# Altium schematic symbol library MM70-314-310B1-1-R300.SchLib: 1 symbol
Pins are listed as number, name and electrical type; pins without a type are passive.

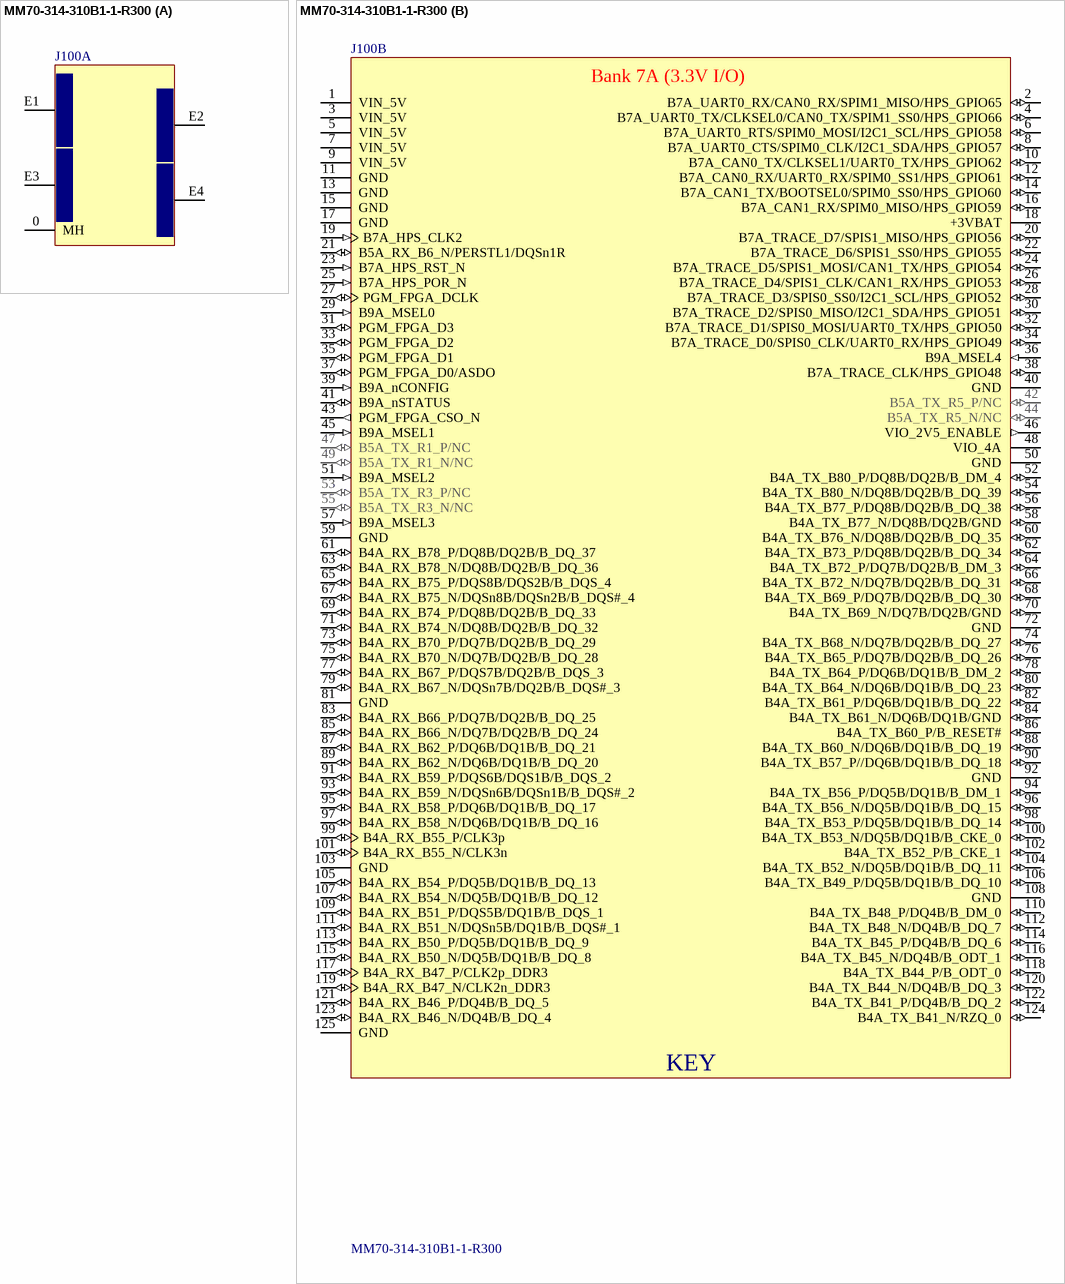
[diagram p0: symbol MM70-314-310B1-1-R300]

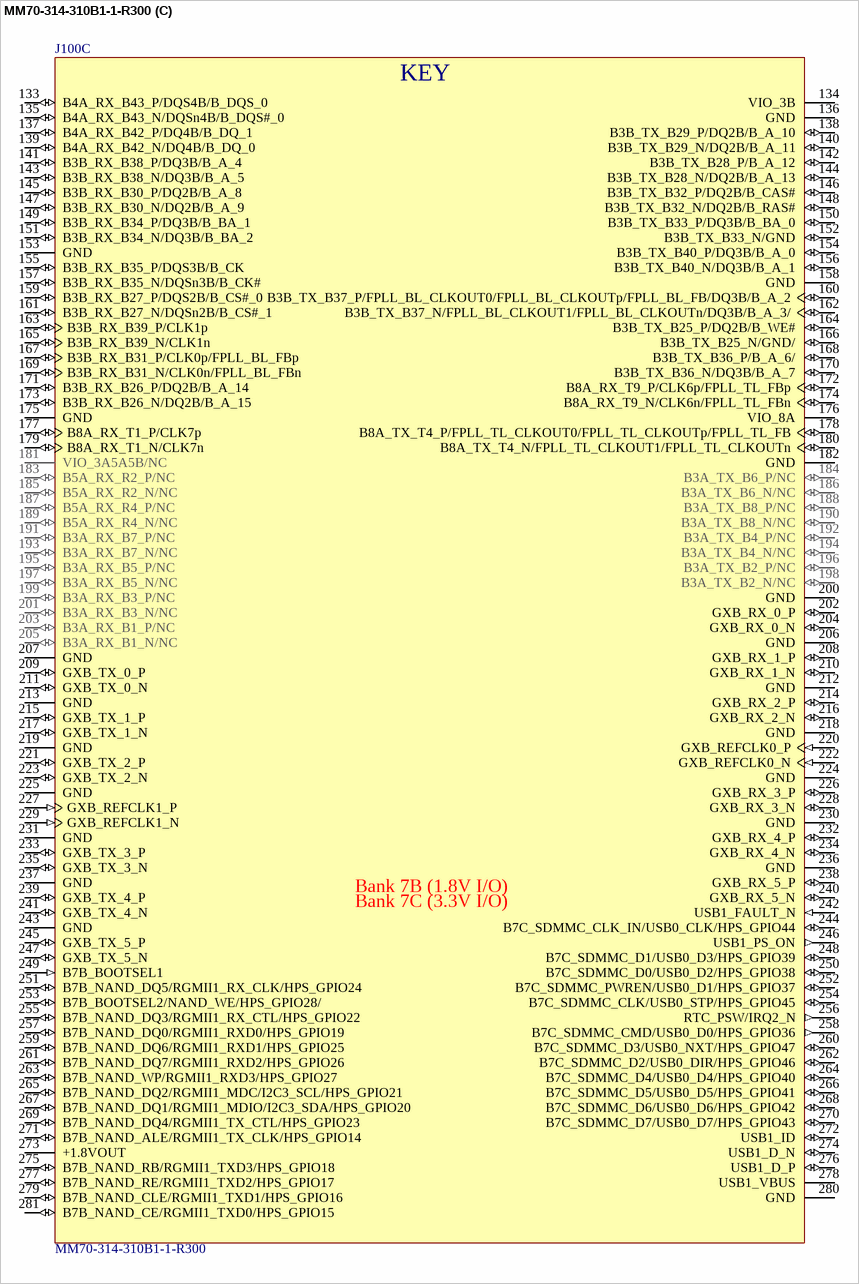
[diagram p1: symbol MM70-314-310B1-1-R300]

## MM70-314-310B1-1-R300
designator J100
MEM SOCKET 314POS RT ANG GOLD; Mfg: JAE Electronics; Dist1_PN: 670-2431-1-ND; Dist1: Digi-Key; User: Huy; $/10: 9.320000; $/100: 6.096200; Mfg_PID: 9534; PbFree_Status: Lead free; QtyAvail: 784; ID: 7823
footprint MM70-314-310B1
part A pins: 0 MH (power), E1 (power), E2 (power), E3 (power), E4 (power)
part B pins: 1 VIN_5V (power), 2 B7A_UART0_RX/CAN0_RX/SPIM1_MISO/HPS_GPIO65 (io), 3 VIN_5V (power), 4 B7A_UART0_TX/CLKSEL0/CAN0_TX/SPIM1_SS0/HPS_GPIO66 (io), 5 VIN_5V (power), 6 B7A_UART0_RTS/SPIM0_MOSI/I2C1_SCL/HPS_GPIO58 (io), 7 VIN_5V (power), 8 B7A_UART0_CTS/SPIM0_CLK/I2C1_SDA/HPS_GPIO57 (io), 9 VIN_5V (power), 10 B7A_CAN0_TX/CLKSEL1/UART0_TX/HPS_GPIO62 (io), 11 GND (power), 12 B7A_CAN0_RX/UART0_RX/SPIM0_SS1/HPS_GPIO61 (io), 13 GND (power), 14 B7A_CAN1_TX/BOOTSEL0/SPIM0_SS0/HPS_GPIO60 (io), 15 GND (power), 16 B7A_CAN1_RX/SPIM0_MISO/HPS_GPIO59 (io), 17 GND (power), 18 +3VBAT (power), 19 B7A_HPS_CLK2 (in), 20 B7A_TRACE_D7/SPIS1_MISO/HPS_GPIO56 (io), 21 B5A_RX_B6_N/PERSTL1/DQSn1R (io), 22 B7A_TRACE_D6/SPIS1_SS0/HPS_GPIO55 (io), 23 B7A_HPS_RST_N (in), 24 B7A_TRACE_D5/SPIS1_MOSI/CAN1_TX/HPS_GPIO54 (io), 25 B7A_HPS_POR_N (in), 26 B7A_TRACE_D4/SPIS1_CLK/CAN1_RX/HPS_GPIO53 (io), 27 PGM_FPGA_DCLK (io), 28 B7A_TRACE_D3/SPIS0_SS0/I2C1_SCL/HPS_GPIO52 (io), 29 B9A_MSEL0 (in), 30 B7A_TRACE_D2/SPIS0_MISO/I2C1_SDA/HPS_GPIO51 (io), 31 PGM_FPGA_D3 (io), 32 B7A_TRACE_D1/SPIS0_MOSI/UART0_TX/HPS_GPIO50 (io), 33 PGM_FPGA_D2 (io), 34 B7A_TRACE_D0/SPIS0_CLK/UART0_RX/HPS_GPIO49 (io), 35 PGM_FPGA_D1 (io), 36 B9A_MSEL4 (in), 37 PGM_FPGA_D0/ASDO (io), 38 B7A_TRACE_CLK/HPS_GPIO48 (io), 39 B9A_nCONFIG (in), 40 GND (power), 41 B9A_nSTATUS (io), 42 B5A_TX_R5_P/NC (io), 43 PGM_FPGA_CSO_N (out), 44 B5A_TX_R5_N/NC (io), 45 B9A_MSEL1 (in), 46 VIO_2V5_ENABLE (out), 47 B5A_TX_R1_P/NC (io), 48 VIO_4A (power), 49 B5A_TX_R1_N/NC (io), 50 GND (power), 51 B9A_MSEL2 (in), 52 B4A_TX_B80_P/DQ8B/DQ2B/B_DM_4 (io), 53 B5A_TX_R3_P/NC (io), 54 B4A_TX_B80_N/DQ8B/DQ2B/B_DQ_39 (io), 55 B5A_TX_R3_N/NC (io), 56 B4A_TX_B77_P/DQ8B/DQ2B/B_DQ_38 (io), 57 B9A_MSEL3 (in), 58 B4A_TX_B77_N/DQ8B/DQ2B/GND (io), 59 GND, 60 B4A_TX_B76_N/DQ8B/DQ2B/B_DQ_35 (io), 61 B4A_RX_B78_P/DQ8B/DQ2B/B_DQ_37 (io), 62 B4A_TX_B73_P/DQ8B/DQ2B/B_DQ_34 (io), 63 B4A_RX_B78_N/DQ8B/DQ2B/B_DQ_36 (io), 64 B4A_TX_B72_P/DQ7B/DQ2B/B_DM_3 (io), 65 B4A_RX_B75_P/DQS8B/DQS2B/B_DQS_4 (io), 66 B4A_TX_B72_N/DQ7B/DQ2B/B_DQ_31 (io), 67 B4A_RX_B75_N/DQSn8B/DQSn2B/B_DQS#_4 (io), 68 B4A_TX_B69_P/DQ7B/DQ2B/B_DQ_30 (io), 69 B4A_RX_B74_P/DQ8B/DQ2B/B_DQ_33 (io), 70 B4A_TX_B69_N/DQ7B/DQ2B/GND (io), 71 B4A_RX_B74_N/DQ8B/DQ2B/B_DQ_32 (io), 72 GND (power), 73 B4A_RX_B70_P/DQ7B/DQ2B/B_DQ_29 (io), 74 B4A_TX_B68_N/DQ7B/DQ2B/B_DQ_27 (io), 75 B4A_RX_B70_N/DQ7B/DQ2B/B_DQ_28 (io), 76 B4A_TX_B65_P/DQ7B/DQ2B/B_DQ_26 (io), 77 B4A_RX_B67_P/DQS7B/DQ2B/B_DQS_3 (io), 78 B4A_TX_B64_P/DQ6B/DQ1B/B_DM_2 (io), 79 B4A_RX_B67_N/DQSn7B/DQ2B/B_DQS#_3 (io), 80 B4A_TX_B64_N/DQ6B/DQ1B/B_DQ_23 (io), 81 GND (power), 82 B4A_TX_B61_P/DQ6B/DQ1B/B_DQ_22 (io), 83 B4A_RX_B66_P/DQ7B/DQ2B/B_DQ_25 (io), 84 B4A_TX_B61_N/DQ6B/DQ1B/GND (io), 85 B4A_RX_B66_N/DQ7B/DQ2B/B_DQ_24 (io), 86 B4A_TX_B60_P/B_RESET# (io), 87 B4A_RX_B62_P/DQ6B/DQ1B/B_DQ_21 (io), 88 B4A_TX_B60_N/DQ6B/DQ1B/B_DQ_19 (io), 89 B4A_RX_B62_N/DQ6B/DQ1B/B_DQ_20 (io), 90 B4A_TX_B57_P//DQ6B/DQ1B/B_DQ_18 (io), 91 B4A_RX_B59_P/DQS6B/DQS1B/B_DQS_2 (io), 92 GND (power), 93 B4A_RX_B59_N/DQSn6B/DQSn1B/B_DQS#_2 (io), 94 B4A_TX_B56_P/DQ5B/DQ1B/B_DM_1 (io), 95 B4A_RX_B58_P/DQ6B/DQ1B/B_DQ_17 (io), 96 B4A_TX_B56_N/DQ5B/DQ1B/B_DQ_15 (io), 97 B4A_RX_B58_N/DQ6B/DQ1B/B_DQ_16 (io), 98 B4A_TX_B53_P/DQ5B/DQ1B/B_DQ_14 (io), 99 B4A_RX_B55_P/CLK3p (io), 100 B4A_TX_B53_N/DQ5B/DQ1B/B_CKE_0 (io), 101 B4A_RX_B55_N/CLK3n (io), 102 B4A_TX_B52_P/B_CKE_1 (io), 103 GND (power), 104 B4A_TX_B52_N/DQ5B/DQ1B/B_DQ_11 (io), 105 B4A_RX_B54_P/DQ5B/DQ1B/B_DQ_13 (io), 106 B4A_TX_B49_P/DQ5B/DQ1B/B_DQ_10 (io), 107 B4A_RX_B54_N/DQ5B/DQ1B/B_DQ_12 (io), 108 GND (power), 109 B4A_RX_B51_P/DQS5B/DQ1B/B_DQS_1 (io), 110 B4A_TX_B48_P/DQ4B/B_DM_0 (io), 111 B4A_RX_B51_N/DQSn5B/DQ1B/B_DQS#_1 (io), 112 B4A_TX_B48_N/DQ4B/B_DQ_7 (io), 113 B4A_RX_B50_P/DQ5B/DQ1B/B_DQ_9 (io), 114 B4A_TX_B45_P/DQ4B/B_DQ_6 (io), 115 B4A_RX_B50_N/DQ5B/DQ1B/B_DQ_8 (io), 116 B4A_TX_B45_N/DQ4B/B_ODT_1 (io), 117 B4A_RX_B47_P/CLK2p_DDR3 (io), 118 B4A_TX_B44_P/B_ODT_0 (io), 119 B4A_RX_B47_N/CLK2n_DDR3 (io), 120 B4A_TX_B44_N/DQ4B/B_DQ_3 (io), 121 B4A_RX_B46_P/DQ4B/B_DQ_5 (io), 122 B4A_TX_B41_P/DQ4B/B_DQ_2 (io), 123 B4A_RX_B46_N/DQ4B/B_DQ_4 (io), 124 B4A_TX_B41_N/RZQ_0 (io), 125 GND (power)
part C pins: 133 B4A_RX_B43_P/DQS4B/B_DQS_0 (io), 134 VIO_3B (power), 135 B4A_RX_B43_N/DQSn4B/B_DQS#_0 (io), 136 GND (power), 137 B4A_RX_B42_P/DQ4B/B_DQ_1 (io), 138 B3B_TX_B29_P/DQ2B/B_A_10 (io), 139 B4A_RX_B42_N/DQ4B/B_DQ_0 (io), 140 B3B_TX_B29_N/DQ2B/B_A_11 (io), 141 B3B_RX_B38_P/DQ3B/B_A_4 (io), 142 B3B_TX_B28_P/B_A_12 (io), 143 B3B_RX_B38_N/DQ3B/B_A_5 (io), 144 B3B_TX_B28_N/DQ2B/B_A_13 (io), 145 B3B_RX_B30_P/DQ2B/B_A_8 (io), 146 B3B_TX_B32_P/DQ2B/B_CAS# (io), 147 B3B_RX_B30_N/DQ2B/B_A_9 (io), 148 B3B_TX_B32_N/DQ2B/B_RAS# (io), 149 B3B_RX_B34_P/DQ3B/B_BA_1 (io), 150 B3B_TX_B33_P/DQ3B/B_BA_0 (io), 151 B3B_RX_B34_N/DQ3B/B_BA_2 (io), 152 B3B_TX_B33_N/GND (io), 153 GND (power), 154 B3B_TX_B40_P/DQ3B/B_A_0 (io), 155 B3B_RX_B35_P/DQS3B/B_CK (io), 156 B3B_TX_B40_N/DQ3B/B_A_1 (io), 157 B3B_RX_B35_N/DQSn3B/B_CK# (io), 158 GND (power), 159 B3B_RX_B27_P/DQS2B/B_CS#_0 (io), 160 B3B_TX_B37_P/FPLL_BL_CLKOUT0/FPLL_BL_CLKOUTp/FPLL_BL_FB/DQ3B/B_A_2 (io), 161 B3B_RX_B27_N/DQSn2B/B_CS#_1 (io), 162 B3B_TX_B37_N/FPLL_BL_CLKOUT1/FPLL_BL_CLKOUTn/DQ3B/B_A_3/ (io), 163 B3B_RX_B39_P/CLK1p (io), 164 B3B_TX_B25_P/DQ2B/B_WE# (io), 165 B3B_RX_B39_N/CLK1n (io), 166 B3B_TX_B25_N/GND/ (io), 167 B3B_RX_B31_P/CLK0p/FPLL_BL_FBp (io), 168 B3B_TX_B36_P/B_A_6/ (io), 169 B3B_RX_B31_N/CLK0n/FPLL_BL_FBn (io), 170 B3B_TX_B36_N/DQ3B/B_A_7 (io), 171 B3B_RX_B26_P/DQ2B/B_A_14 (io), 172 B8A_RX_T9_P/CLK6p/FPLL_TL_FBp (io), 173 B3B_RX_B26_N/DQ2B/B_A_15 (io), 174 B8A_RX_T9_N/CLK6n/FPLL_TL_FBn (io), 175 GND (power), 176 VIO_8A (power), 177 B8A_RX_T1_P/CLK7p (io), 178 B8A_TX_T4_P/FPLL_TL_CLKOUT0/FPLL_TL_CLKOUTp/FPLL_TL_FB (io), 179 B8A_RX_T1_N/CLK7n (io), 180 B8A_TX_T4_N/FPLL_TL_CLKOUT1/FPLL_TL_CLKOUTn (io), 181 VIO_3A5A5B/NC, 182 GND (power), 183 B5A_RX_R2_P/NC (io), 184 B3A_TX_B6_P/NC (io), 185 B5A_RX_R2_N/NC (io), 186 B3A_TX_B6_N/NC (io), 187 B5A_RX_R4_P/NC (io), 188 B3A_TX_B8_P/NC (io), 189 B5A_RX_R4_N/NC (io), 190 B3A_TX_B8_N/NC (io), 191 B3A_RX_B7_P/NC (io), 192 B3A_TX_B4_P/NC (io), 193 B3A_RX_B7_N/NC (io), 194 B3A_TX_B4_N/NC (io), 195 B3A_RX_B5_P/NC (io), 196 B3A_TX_B2_P/NC (io), 197 B3A_RX_B5_N/NC (io), 198 B3A_TX_B2_N/NC (io), 199 B3A_RX_B3_P/NC (io), 200 GND (power), 201 B3A_RX_B3_N/NC (io), 202 GXB_RX_0_P (io), 203 B3A_RX_B1_P/NC (io), 204 GXB_RX_0_N (io), 205 B3A_RX_B1_N/NC (io), 206 GND (power), 207 GND (power), 208 GXB_RX_1_P (io), 209 GXB_TX_0_P (io), 210 GXB_RX_1_N (io), 211 GXB_TX_0_N (io), 212 GND (power), 213 GND (power), 214 GXB_RX_2_P (io), 215 GXB_TX_1_P (io), 216 GXB_RX_2_N (io), 217 GXB_TX_1_N (io), 218 GND (power), 219 GND (power), 220 GXB_REFCLK0_P (in), 221 GXB_TX_2_P (io), 222 GXB_REFCLK0_N (in), 223 GXB_TX_2_N (io), 224 GND (power), 225 GND (power), 226 GXB_RX_3_P (io), 227 GXB_REFCLK1_P (in), 228 GXB_RX_3_N (io), 229 GXB_REFCLK1_N (in), 230 GND (power), 231 GND (power), 232 GXB_RX_4_P (io), 233 GXB_TX_3_P (io), 234 GXB_RX_4_N (io), 235 GXB_TX_3_N (io), 236 GND (power), 237 GND (power), 238 GXB_RX_5_P (io), 239 GXB_TX_4_P (io), 240 GXB_RX_5_N (io), 241 GXB_TX_4_N (io), 242 USB1_FAULT_N (in), 243 GND (power), 244 B7C_SDMMC_CLK_IN/USB0_CLK/HPS_GPIO44 (io), 245 GXB_TX_5_P (io), 246 USB1_PS_ON (out), 247 GXB_TX_5_N (io), 248 B7C_SDMMC_D1/USB0_D3/HPS_GPIO39 (io), 249 B7B_BOOTSEL1 (in), 250 B7C_SDMMC_D0/USB0_D2/HPS_GPIO38 (io), 251 B7B_NAND_DQ5/RGMII1_RX_CLK/HPS_GPIO24 (io), 252 B7C_SDMMC_PWREN/USB0_D1/HPS_GPIO37 (io), 253 B7B_BOOTSEL2/NAND_WE/HPS_GPIO28/ (io), 254 B7C_SDMMC_CLK/USB0_STP/HPS_GPIO45 (io), 255 B7B_NAND_DQ3/RGMII1_RX_CTL/HPS_GPIO22 (io), 256 RTC_PSW/IRQ2_N (out), 257 B7B_NAND_DQ0/RGMII1_RXD0/HPS_GPIO19 (io), 258 B7C_SDMMC_CMD/USB0_D0/HPS_GPIO36 (out), 259 B7B_NAND_DQ6/RGMII1_RXD1/HPS_GPIO25 (io), 260 B7C_SDMMC_D3/USB0_NXT/HPS_GPIO47 (io), 261 B7B_NAND_DQ7/RGMII1_RXD2/HPS_GPIO26 (io), 262 B7C_SDMMC_D2/USB0_DIR/HPS_GPIO46 (io), 263 B7B_NAND_WP/RGMII1_RXD3/HPS_GPIO27 (io), 264 B7C_SDMMC_D4/USB0_D4/HPS_GPIO40 (io), 265 B7B_NAND_DQ2/RGMII1_MDC/I2C3_SCL/HPS_GPIO21 (io), 266 B7C_SDMMC_D5/USB0_D5/HPS_GPIO41 (io), 267 B7B_NAND_DQ1/RGMII1_MDIO/I2C3_SDA/HPS_GPIO20 (io), 268 B7C_SDMMC_D6/USB0_D6/HPS_GPIO42 (io), 269 B7B_NAND_DQ4/RGMII1_TX_CTL/HPS_GPIO23 (io), 270 B7C_SDMMC_D7/USB0_D7/HPS_GPIO43 (io), 271 B7B_NAND_ALE/RGMII1_TX_CLK/HPS_GPIO14 (io), 272 USB1_ID (io), 273 +1.8VOUT (power), 274 USB1_D_N (io), 275 B7B_NAND_RB/RGMII1_TXD3/HPS_GPIO18 (io), 276 USB1_D_P (io), 277 B7B_NAND_RE/RGMII1_TXD2/HPS_GPIO17 (io), 278 USB1_VBUS (power), 279 B7B_NAND_CLE/RGMII1_TXD1/HPS_GPIO16 (io), 280 GND (power), 281 B7B_NAND_CE/RGMII1_TXD0/HPS_GPIO15 (io)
